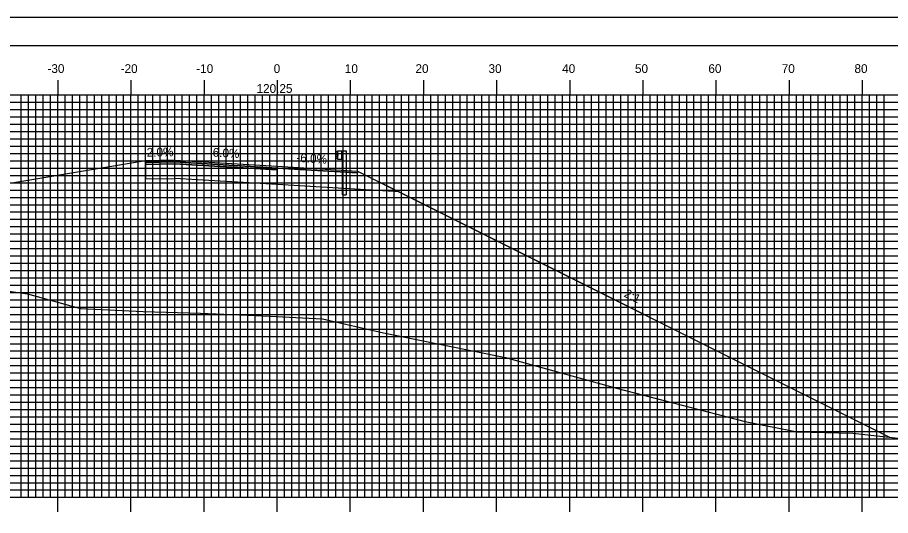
# Model space of a CAD drawing. Extents: x 856478 to 856821, y 364366 to 364586.
# Drawn here: x 856607.8 to 856727.2, y 364517.6 to 364585.7 of the extents above; entities that cross this region are included whole.
import ezdxf

# ---------------------------------------------------------------- set-up
doc = ezdxf.new("R2010")
doc.units = 0
for name, color, linetype in [('ANNOTATION', 7, 'Continuous'), ('BORDER', 7, 'Continuous'), ('D_Guardrail_Beam_Rt', 7, 'Continuous'), ('D_Roadway_Centerline', 7, 'Continuous'), ('D_Roadway_Centerline_Text', 7, 'Continuous'), ('D_Roadway_Edge_Shoulder', 7, 'Continuous'), ('D_Roadway_Edge_TW', 7, 'Continuous'), ('D_Roadway_Pavement', 7, 'Continuous'), ('D_Roadway_SlopeLines', 7, 'Continuous'), ('D_Roadway_SubGrade', 7, 'Continuous'), ('H_V ANNOTATION', 7, 'Continuous'), ('M_Utilities_Pole', 7, 'Continuous'), ('MAJOR', 7, 'Continuous'), ('MINOR', 7, 'Continuous'), ('PLOT BOUNDARY', 7, 'Continuous'), ('S_Roadway_Centerline', 7, 'Continuous')]:
    doc.layers.add(name, color=color, linetype=linetype)

msp = doc.modelspace()

# ---------------------------------------------------------------- linework, layer by layer
at = {"layer": 'BORDER'}
msp.add_lwpolyline([(856493.71, 364371.79), (856813.71, 364371.79), (856813.71, 364581.79), (856493.71, 364581.79)], close=True, dxfattribs=at)
at = {"layer": 'D_Guardrail_Beam_Rt'}
for p, q in [((856651.49, 364567.33), (856651.35, 364567.23)), ((856651.35, 364567.09), (856651.54, 364566.95)), ((856651.54, 364566.75), (856651.35, 364566.61)), ((856651.35, 364566.47), (856651.49, 364566.37)), ((856651.58, 364567.35), (856651.51, 364567.34)), ((856651.51, 364566.36), (856651.58, 364566.35)), ((856651.58, 364567.43), (856652.27, 364567.43)), ((856651.58, 364566.27), (856651.58, 364567.43)), ((856651.58, 364566.89), (856651.58, 364566.81)), ((856652.1, 364567.43), (856652.1, 364566.27)), ((856652.21, 364567.43), (856652.21, 364566.27)), ((856652.27, 364567.43), (856652.74, 364567.43)), ((856652.27, 364567.43), (856652.27, 364566.27)), ((856652.74, 364567.43), (856652.74, 364561.43)), ((856652.27, 364566.27), (856651.58, 364566.27)), ((856652.25, 364561.43), (856652.25, 364566.27)), ((856652.25, 364561.43), (856652.74, 364561.43))]:
    msp.add_line(p, q, dxfattribs=at)
for centre, major_axis, start_param, end_param in [((856651.4, 364567.16), (-0.0877, 0), 5.323254, 7.243116), ((856651.4, 364566.54), (-0.0877, 0), 5.323254, 7.243116), ((856651.51, 364567.29), (-0.0417, 0), 4.907132, 5.323254), ((856651.51, 364566.41), (-0.0417, 0), 0.959931, 1.376053), ((856651.5, 364566.89), (0.0789, 0), 0, 0.959931), ((856651.5, 364566.81), (0.0789, 0), 5.323254, 6.283185)]:
    msp.add_ellipse(centre, major_axis=major_axis, ratio=0.995501, start_param=start_param, end_param=end_param, dxfattribs=at)
at = {"layer": 'D_Roadway_Centerline'}
msp.add_lwpolyline([(856625.31, 364566.09), (856629.31, 364566.17), (856643.31, 364565.33), (856651.31, 364564.85), (856654.31, 364564.67), (856659.99, 364561.83), (856727.07, 364528.29)], dxfattribs=at)
at = {"layer": 'D_Roadway_Edge_Shoulder'}
for points in [[(856629.31, 364566.17), (856625.31, 364566.09), (856625.31, 364565.84), (856629.31, 364565.92)], [(856643.31, 364565.33), (856651.31, 364564.85), (856651.31, 364564.85), (856654.31, 364564.67), (856654.31, 364564.42), (856643.31, 364565.08)]]:
    msp.add_lwpolyline(points, close=True, dxfattribs=at)
at = {"layer": 'D_Roadway_Edge_TW'}
msp.add_lwpolyline([(856629.31, 364566.17), (856643.31, 364565.33), (856643.31, 364565.08), (856629.31, 364565.92)], close=True, dxfattribs=at)
at = {"layer": 'D_Roadway_Pavement'}
for points in [[(856629.31, 364565.92), (856625.31, 364565.84), (856625.31, 364565.59), (856629.31, 364565.67)], [(856629.31, 364565.92), (856643.31, 364565.08), (856643.31, 364564.83), (856629.31, 364565.67)]]:
    msp.add_lwpolyline(points, close=True, dxfattribs=at)
msp.add_lwpolyline([(856643.31, 364565.08), (856643.31, 364564.83)], dxfattribs=at)
msp.add_lwpolyline([(856643.31, 364565.08), (856643.31, 364564.83)], dxfattribs=at)
at = {"layer": 'D_Roadway_SlopeLines'}
for points in [[(856625.31, 364566.09), (856576.95, 364558.03)], [(856654.31, 364564.67), (856727.07, 364528.29)]]:
    msp.add_lwpolyline(points, dxfattribs=at)
at = {"layer": 'D_Roadway_SubGrade'}
for points in [[(856629.31, 364565.67), (856625.31, 364565.59), (856625.31, 364565.84), (856625.31, 364566.09), (856625.31, 364563.59), (856629.31, 364563.67)], [(856629.31, 364565.67), (856643.31, 364564.83), (856643.31, 364562.83), (856629.31, 364563.67)], [(856643.31, 364564.83), (856643.31, 364565.08), (856654.31, 364564.42), (856654.31, 364564.67), (856659.99, 364561.83), (856643.31, 364562.83)]]:
    msp.add_lwpolyline(points, close=True, dxfattribs=at)
at = {"layer": 'M_Utilities_Pole'}
msp.add_line((856664.36, 364543.03), (856664.36, 364543.01), dxfattribs=at)
msp.add_circle((856664.36, 364543.02), 0.00417, dxfattribs=at)
at = {"layer": 'MAJOR'}
for p, q in [((856613.31, 364577.09), (856613.31, 364575.08)), ((856623.31, 364577.09), (856623.31, 364575.08)), ((856633.31, 364577.09), (856633.31, 364575.08)), ((856643.31, 364577.09), (856643.31, 364575.08)), ((856653.31, 364577.09), (856653.31, 364575.08)), ((856663.31, 364577.09), (856663.31, 364575.08)), ((856673.31, 364577.09), (856673.31, 364575.08)), ((856683.31, 364577.09), (856683.31, 364575.08)), ((856693.31, 364577.09), (856693.31, 364575.08)), ((856703.31, 364577.09), (856703.31, 364575.08)), ((856713.31, 364577.09), (856713.31, 364575.08)), ((856723.31, 364577.09), (856723.31, 364575.08)), ((856503.31, 364575.08), (856783.31, 364575.08)), ((856503.31, 364575.08), (856783.31, 364575.08)), ((856613.31, 364520.08), (856613.31, 364575.08)), ((856623.31, 364520.08), (856623.31, 364575.08)), ((856633.31, 364520.08), (856633.31, 364575.08)), ((856643.31, 364520.08), (856643.31, 364575.08)), ((856653.31, 364520.08), (856653.31, 364575.08)), ((856663.31, 364520.08), (856663.31, 364575.08)), ((856673.31, 364520.08), (856673.31, 364575.08)), ((856683.31, 364520.08), (856683.31, 364575.08)), ((856693.31, 364520.08), (856693.31, 364575.08)), ((856703.31, 364520.08), (856703.31, 364575.08)), ((856713.31, 364520.08), (856713.31, 364575.08)), ((856723.31, 364520.08), (856723.31, 364575.08)), ((856503.31, 364570.08), (856783.31, 364570.08)), ((856503.31, 364565.08), (856783.31, 364565.08)), ((856503.31, 364560.08), (856783.31, 364560.08)), ((856503.31, 364555.08), (856783.31, 364555.08)), ((856503.31, 364550.08), (856783.31, 364550.08)), ((856503.31, 364545.08), (856783.31, 364545.08)), ((856503.31, 364540.08), (856783.31, 364540.08)), ((856503.31, 364535.08), (856783.31, 364535.08)), ((856503.31, 364530.08), (856783.31, 364530.08)), ((856503.31, 364525.08), (856783.31, 364525.08)), ((856503.31, 364520.08), (856783.31, 364520.08)), ((856503.31, 364520.08), (856783.31, 364520.08)), ((856613.31, 364518.08), (856613.31, 364520.08)), ((856623.31, 364518.08), (856623.31, 364520.08)), ((856633.31, 364518.08), (856633.31, 364520.08)), ((856643.31, 364518.08), (856643.31, 364520.08)), ((856653.31, 364518.08), (856653.31, 364520.08)), ((856663.31, 364518.08), (856663.31, 364520.08)), ((856673.31, 364518.08), (856673.31, 364520.08)), ((856683.31, 364518.08), (856683.31, 364520.08)), ((856693.31, 364518.08), (856693.31, 364520.08)), ((856703.31, 364518.08), (856703.31, 364520.08)), ((856713.31, 364518.08), (856713.31, 364520.08)), ((856723.31, 364518.08), (856723.31, 364520.08))]:
    msp.add_line(p, q, dxfattribs=at)
at = {"layer": 'MINOR'}
for p, q in [((856608.31, 364520.08), (856608.31, 364575.08)), ((856609.31, 364520.08), (856609.31, 364575.08)), ((856610.31, 364520.08), (856610.31, 364575.08)), ((856611.31, 364520.08), (856611.31, 364575.08)), ((856612.31, 364520.08), (856612.31, 364575.08)), ((856614.31, 364520.08), (856614.31, 364575.08)), ((856615.31, 364520.08), (856615.31, 364575.08)), ((856616.31, 364520.08), (856616.31, 364575.08)), ((856617.31, 364520.08), (856617.31, 364575.08)), ((856618.31, 364520.08), (856618.31, 364575.08)), ((856619.31, 364520.08), (856619.31, 364575.08)), ((856620.31, 364520.08), (856620.31, 364575.08)), ((856621.31, 364520.08), (856621.31, 364575.08)), ((856622.31, 364520.08), (856622.31, 364575.08)), ((856624.31, 364520.08), (856624.31, 364575.08)), ((856625.31, 364520.08), (856625.31, 364575.08)), ((856626.31, 364520.08), (856626.31, 364575.08)), ((856627.31, 364520.08), (856627.31, 364575.08)), ((856628.31, 364520.08), (856628.31, 364575.08)), ((856629.31, 364520.08), (856629.31, 364575.08)), ((856630.31, 364520.08), (856630.31, 364575.08)), ((856631.31, 364520.08), (856631.31, 364575.08)), ((856632.31, 364520.08), (856632.31, 364575.08)), ((856634.31, 364520.08), (856634.31, 364575.08)), ((856635.31, 364520.08), (856635.31, 364575.08)), ((856636.31, 364520.08), (856636.31, 364575.08)), ((856637.31, 364520.08), (856637.31, 364575.08)), ((856638.31, 364520.08), (856638.31, 364575.08)), ((856639.31, 364520.08), (856639.31, 364575.08)), ((856640.31, 364520.08), (856640.31, 364575.08)), ((856641.31, 364520.08), (856641.31, 364575.08)), ((856642.31, 364520.08), (856642.31, 364575.08)), ((856644.31, 364520.08), (856644.31, 364575.08)), ((856645.31, 364520.08), (856645.31, 364575.08)), ((856646.31, 364520.08), (856646.31, 364575.08)), ((856647.31, 364520.08), (856647.31, 364575.08)), ((856648.31, 364520.08), (856648.31, 364575.08)), ((856649.31, 364520.08), (856649.31, 364575.08)), ((856650.31, 364520.08), (856650.31, 364575.08)), ((856651.31, 364520.08), (856651.31, 364575.08)), ((856652.31, 364520.08), (856652.31, 364575.08)), ((856654.31, 364520.08), (856654.31, 364575.08)), ((856655.31, 364520.08), (856655.31, 364575.08)), ((856656.31, 364520.08), (856656.31, 364575.08)), ((856657.31, 364520.08), (856657.31, 364575.08)), ((856658.31, 364520.08), (856658.31, 364575.08)), ((856659.31, 364520.08), (856659.31, 364575.08)), ((856660.31, 364520.08), (856660.31, 364575.08)), ((856661.31, 364520.08), (856661.31, 364575.08)), ((856662.31, 364520.08), (856662.31, 364575.08)), ((856664.31, 364520.08), (856664.31, 364575.08)), ((856665.31, 364520.08), (856665.31, 364575.08)), ((856666.31, 364520.08), (856666.31, 364575.08)), ((856667.31, 364520.08), (856667.31, 364575.08)), ((856668.31, 364520.08), (856668.31, 364575.08)), ((856669.31, 364520.08), (856669.31, 364575.08)), ((856670.31, 364520.08), (856670.31, 364575.08)), ((856671.31, 364520.08), (856671.31, 364575.08)), ((856672.31, 364520.08), (856672.31, 364575.08)), ((856674.31, 364520.08), (856674.31, 364575.08)), ((856675.31, 364520.08), (856675.31, 364575.08)), ((856676.31, 364520.08), (856676.31, 364575.08)), ((856677.31, 364520.08), (856677.31, 364575.08)), ((856678.31, 364520.08), (856678.31, 364575.08)), ((856679.31, 364520.08), (856679.31, 364575.08)), ((856680.31, 364520.08), (856680.31, 364575.08)), ((856681.31, 364520.08), (856681.31, 364575.08)), ((856682.31, 364520.08), (856682.31, 364575.08)), ((856684.31, 364520.08), (856684.31, 364575.08)), ((856685.31, 364520.08), (856685.31, 364575.08)), ((856686.31, 364520.08), (856686.31, 364575.08)), ((856687.31, 364520.08), (856687.31, 364575.08)), ((856688.31, 364520.08), (856688.31, 364575.08)), ((856689.31, 364520.08), (856689.31, 364575.08)), ((856690.31, 364520.08), (856690.31, 364575.08)), ((856691.31, 364520.08), (856691.31, 364575.08)), ((856692.31, 364520.08), (856692.31, 364575.08)), ((856694.31, 364520.08), (856694.31, 364575.08)), ((856695.31, 364520.08), (856695.31, 364575.08)), ((856696.31, 364520.08), (856696.31, 364575.08)), ((856697.31, 364520.08), (856697.31, 364575.08)), ((856698.31, 364520.08), (856698.31, 364575.08)), ((856699.31, 364520.08), (856699.31, 364575.08)), ((856700.31, 364520.08), (856700.31, 364575.08)), ((856701.31, 364520.08), (856701.31, 364575.08)), ((856702.31, 364520.08), (856702.31, 364575.08)), ((856704.31, 364520.08), (856704.31, 364575.08)), ((856705.31, 364520.08), (856705.31, 364575.08)), ((856706.31, 364520.08), (856706.31, 364575.08)), ((856707.31, 364520.08), (856707.31, 364575.08)), ((856708.31, 364520.08), (856708.31, 364575.08)), ((856709.31, 364520.08), (856709.31, 364575.08)), ((856710.31, 364520.08), (856710.31, 364575.08)), ((856711.31, 364520.08), (856711.31, 364575.08)), ((856712.31, 364520.08), (856712.31, 364575.08)), ((856714.31, 364520.08), (856714.31, 364575.08)), ((856715.31, 364520.08), (856715.31, 364575.08)), ((856716.31, 364520.08), (856716.31, 364575.08)), ((856717.31, 364520.08), (856717.31, 364575.08)), ((856718.31, 364520.08), (856718.31, 364575.08)), ((856719.31, 364520.08), (856719.31, 364575.08)), ((856720.31, 364520.08), (856720.31, 364575.08)), ((856721.31, 364520.08), (856721.31, 364575.08)), ((856722.31, 364520.08), (856722.31, 364575.08)), ((856724.31, 364520.08), (856724.31, 364575.08)), ((856725.31, 364520.08), (856725.31, 364575.08)), ((856726.31, 364520.08), (856726.31, 364575.08)), ((856503.31, 364574.08), (856783.31, 364574.08)), ((856503.31, 364573.08), (856783.31, 364573.08)), ((856503.31, 364572.08), (856783.31, 364572.08)), ((856503.31, 364571.08), (856783.31, 364571.08)), ((856503.31, 364569.08), (856783.31, 364569.08)), ((856503.31, 364568.08), (856783.31, 364568.08)), ((856503.31, 364567.08), (856783.31, 364567.08)), ((856503.31, 364566.08), (856783.31, 364566.08)), ((856503.31, 364564.08), (856783.31, 364564.08)), ((856503.31, 364563.08), (856783.31, 364563.08)), ((856503.31, 364562.08), (856783.31, 364562.08)), ((856503.31, 364561.08), (856783.31, 364561.08)), ((856503.31, 364559.08), (856783.31, 364559.08)), ((856503.31, 364558.08), (856783.31, 364558.08)), ((856503.31, 364557.08), (856783.31, 364557.08)), ((856503.31, 364556.08), (856783.31, 364556.08)), ((856503.31, 364554.08), (856783.31, 364554.08)), ((856503.31, 364553.08), (856783.31, 364553.08)), ((856503.31, 364552.08), (856783.31, 364552.08)), ((856503.31, 364551.08), (856783.31, 364551.08)), ((856503.31, 364549.08), (856783.31, 364549.08)), ((856503.31, 364548.08), (856783.31, 364548.08)), ((856503.31, 364547.08), (856783.31, 364547.08)), ((856503.31, 364546.08), (856783.31, 364546.08)), ((856503.31, 364544.08), (856783.31, 364544.08)), ((856503.31, 364543.08), (856783.31, 364543.08)), ((856503.31, 364542.08), (856783.31, 364542.08)), ((856503.31, 364541.08), (856783.31, 364541.08)), ((856503.31, 364539.08), (856783.31, 364539.08)), ((856503.31, 364538.08), (856783.31, 364538.08)), ((856503.31, 364537.08), (856783.31, 364537.08)), ((856503.31, 364536.08), (856783.31, 364536.08)), ((856503.31, 364534.08), (856783.31, 364534.08)), ((856503.31, 364533.08), (856783.31, 364533.08)), ((856503.31, 364532.08), (856783.31, 364532.08)), ((856503.31, 364531.08), (856783.31, 364531.08)), ((856503.31, 364529.08), (856783.31, 364529.08)), ((856503.31, 364528.08), (856783.31, 364528.08)), ((856503.31, 364527.08), (856783.31, 364527.08)), ((856503.31, 364526.08), (856783.31, 364526.08)), ((856503.31, 364524.08), (856783.31, 364524.08)), ((856503.31, 364523.08), (856783.31, 364523.08)), ((856503.31, 364522.08), (856783.31, 364522.08)), ((856503.31, 364521.08), (856783.31, 364521.08))]:
    msp.add_line(p, q, dxfattribs=at)
at = {"layer": 'PLOT BOUNDARY'}
msp.add_lwpolyline([(856477.52, 364365.67), (856817.52, 364365.67), (856817.52, 364585.67), (856477.52, 364585.67)], close=True, dxfattribs=at)
at = {"layer": 'S_Roadway_Centerline'}
msp.add_lwpolyline([(856600.75, 364549.07), (856609.18, 364547.9), (856616.41, 364545.87), (856624.97, 364545.49), (856632.8, 364545.27), (856641.36, 364544.87), (856649.52, 364544.46), (856657.83, 364542.58), (856674.51, 364539.19), (856689.71, 364535.01), (856707.33, 364530.44), (856714.43, 364529.03), (856722.05, 364528.83), (856731.51, 364527.81), (856738.52, 364527.64), (856746.86, 364527.14), (856752.42, 364527.12), (856757.29, 364526.99), (856763.74, 364526.99), (856773.12, 364527.14), (856779.07, 364527.12), (856783.31, 364527.24)], dxfattribs=at)

# ---------------------------------------------------------------- texts
at = {"layer": 'ANNOTATION'}
for s, rotation, p in [('-2.0%', 1.1458, (856624.94, 364566.62)), ('6.0%', 356.5664, (856634.46, 364566.66)), ('-6.0%', 356.5664, (856645.9, 364565.93)), ('2:1', 333.4349, (856690.63, 364547.55))]:
    msp.add_text(s, height=1.2, rotation=rotation, dxfattribs=at).set_placement(p)
at = {"layer": 'D_Roadway_Centerline_Text'}
msp.add_text('120.25', height=1.2, dxfattribs=at).set_placement((856640.49, 364575.36))
at = {"layer": 'H_V ANNOTATION'}
for s, p in [('-30', (856611.89, 364578.08)), ('-20', (856621.9, 364578.08)), ('-10', (856632.24, 364578.08)), ('0', (856642.83, 364578.08)), ('10', (856652.56, 364578.08)), ('20', (856662.22, 364578.08)), ('30', (856672.21, 364578.08)), ('40', (856682.28, 364578.08)), ('50', (856692.24, 364578.08)), ('60', (856702.28, 364578.08)), ('70', (856712.31, 364578.08)), ('80', (856722.26, 364578.08))]:
    msp.add_text(s, height=1.2, dxfattribs=at).set_placement(p)

doc.saveas('drawing.dxf')
